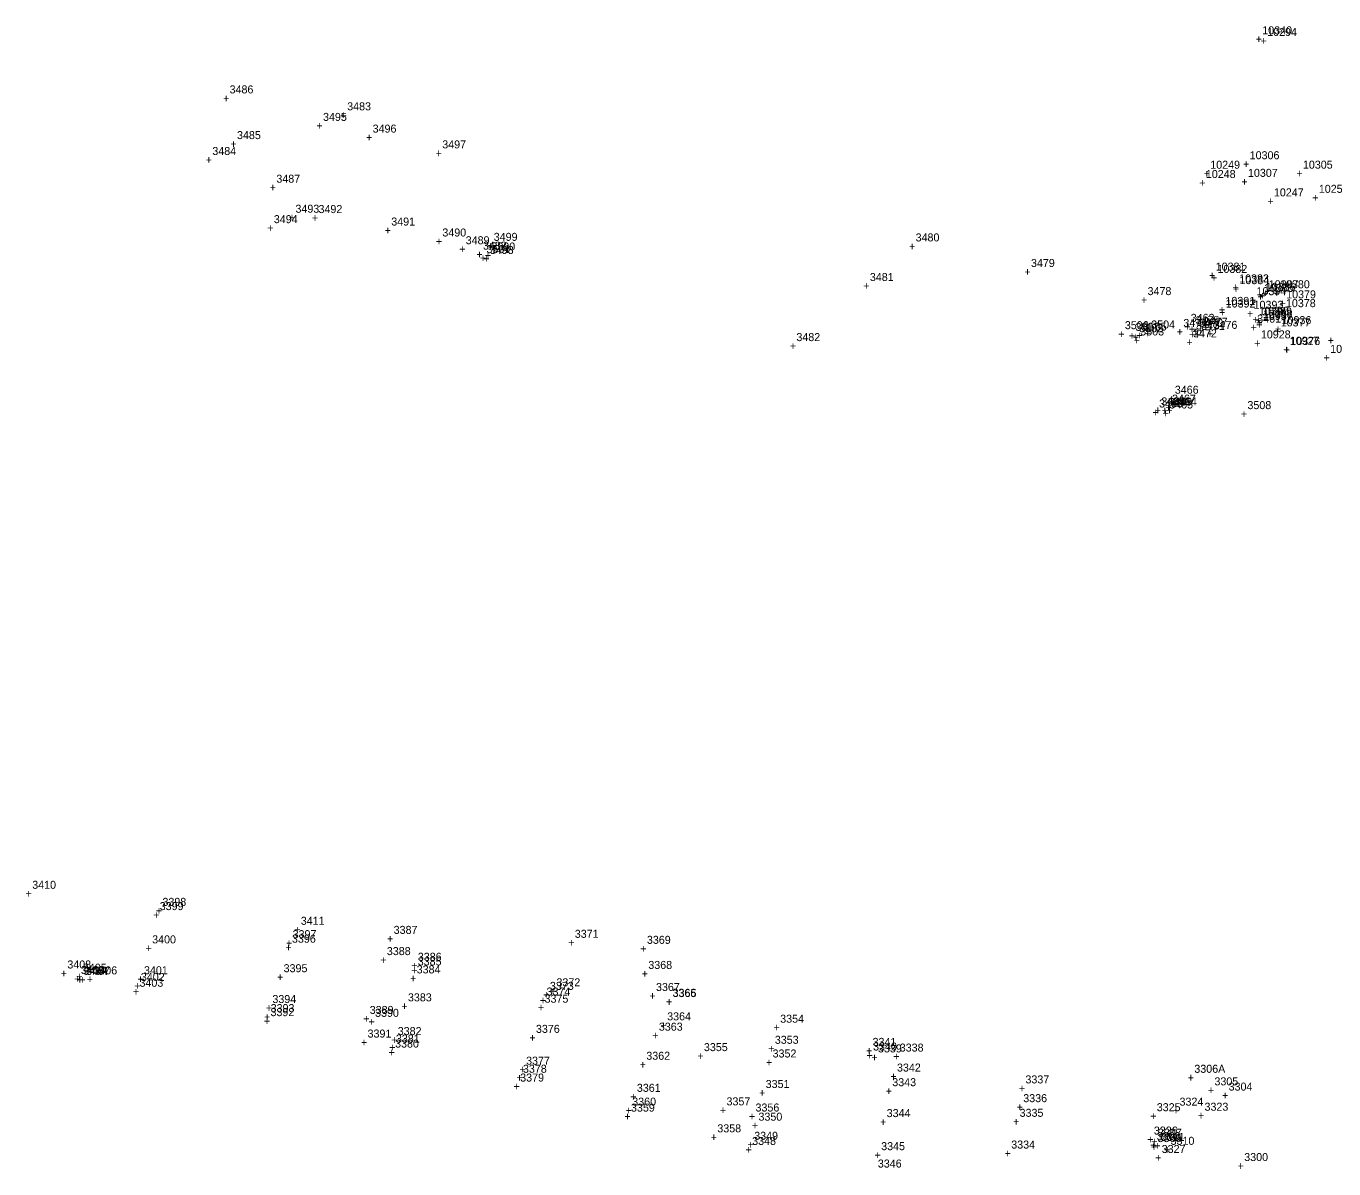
# Model space of a CAD drawing. Extents: x 1136220 to 1137808, y 528804 to 531215.
# Drawn here: x 1136511.5 to 1136920.1, y 529888.9 to 530245.8 of the extents above; entities that cross this region are included whole.
import ezdxf

# ---------------------------------------------------------------- set-up
doc = ezdxf.new("R2010")
doc.units = 0
for name, color, linetype in [('S_Drainage_CB', 7, 'Continuous'), ('S_Drainage_Culvert_Top', 7, 'Continuous'), ('S_Drainage_Invert', 7, 'Continuous'), ('S_Drainage_MH', 7, 'Continuous'), ('S_Drainage_Sump', 7, 'Continuous'), ('S_Fencing_Page', 7, 'Continuous'), ('S_Ground_Elevation', 7, 'Continuous'), ('S_Property_Garden', 7, 'Continuous'), ('S_Railroad_Signal', 7, 'Continuous'), ('S_Railroad_Tracks', 7, 'Continuous'), ('S_RetWall_Top', 7, 'Continuous'), ('S_Roadway_Centerline', 7, 'Continuous'), ('S_Roadway_Drive_Paved', 7, 'Continuous'), ('S_Roadway_Edge_Pavement', 7, 'Continuous'), ('S_Roadway_Sidewalks', 7, 'Continuous'), ('S_Traffic_Sign_DoublePost', 7, 'Continuous'), ('S_Utilities_Gas_Gate', 7, 'Continuous'), ('S_Utilities_UG_Gas_Line', 7, 'Continuous'), ('S_Utilities_UG_Sanitary_MH', 7, 'Continuous'), ('S_Utilities_UG_Water_Gate', 7, 'Continuous'), ('S_Utilities_UG_Water_Line', 7, 'Continuous'), ('S_Utilities_UG_Water_Shutoff', 7, 'Continuous')]:
    doc.layers.add(name, color=color, linetype=linetype)

msp = doc.modelspace()

# ---------------------------------------------------------------- texts
at = {"layer": 'S_Drainage_CB'}
for s, p in [('+', (1136654.33, 530171.88)), ('3498', (1136656.39, 530174.63)), ('3470', (1136878.04, 530151.91)), ('+', (1136875.97, 530149.16)), ('3464', (1136869.84, 530127.3)), ('+', (1136867.77, 530124.55)), ('3404', (1136529.39, 529949.46)), ('+', (1136527.33, 529946.71)), ('3308', (1136864.74, 529897.79)), ('+', (1136862.68, 529895.04))]:
    msp.add_text(s, height=2.5, dxfattribs=at).set_placement(p)
at = {"layer": 'S_Drainage_Culvert_Top'}
for s, p in [('+', (1136655.55, 530175.97)), ('3499', (1136657.61, 530178.72)), ('3506', (1136854.79, 530151.13)), ('3504', (1136863.03, 530151.35)), ('3474', (1136873.06, 530151.83)), ('3476', (1136882.51, 530151.23)), ('+', (1136852.73, 530148.38)), ('+', (1136860.97, 530148.6)), ('+', (1136871, 530149.08)), ('3472', (1136876.09, 530148.57)), ('+', (1136880.45, 530148.48)), ('+', (1136874.03, 530145.82)), ('3466', (1136870.4, 530130.96)), ('3468', (1136865.48, 530126.67)), ('+', (1136868.34, 530128.21)), ('+', (1136863.42, 530123.92)), ('3408', (1136524.4, 529951.44)), ('+', (1136522.33, 529948.69)), ('3406', (1136532.53, 529949.6)), ('+', (1136530.47, 529946.85)), ('3306A', (1136876.5, 529918.85)), ('+', (1136874.44, 529916.1)), ('3310', (1136869.08, 529896.36)), ('+', (1136867.02, 529893.61))]:
    msp.add_text(s, height=2.5, dxfattribs=at).set_placement(p)
at = {"layer": 'S_Drainage_Invert'}
for s, p in [('3500', (1136656.88, 530175.71)), ('+', (1136654.82, 530172.96)), ('3475', (1136876.88, 530152.67)), ('3473', (1136876.95, 530151.04)), ('3477', (1136879.48, 530152.22)), ('+', (1136856.04, 530147.86)), ('3507', (1136858.1, 530150.61)), ('+', (1136858.33, 530147.95)), ('3505', (1136860.4, 530150.7)), ('+', (1136874.82, 530149.92)), ('+', (1136874.89, 530148.29)), ('+', (1136877.42, 530149.47)), ('3469', (1136868.37, 530127.23)), ('3467', (1136869.53, 530128.18)), ('+', (1136866.31, 530124.48)), ('+', (1136867.46, 530125.43)), ('+', (1136526.57, 529946.96)), ('3409', (1136528.63, 529949.71)), ('3407', (1136530.25, 529949.43)), ('+', (1136528.18, 529946.68)), ('3306', (1136876.5, 529918.88)), ('+', (1136874.44, 529916.13)), ('3307', (1136865.12, 529898.89)), ('3311', (1136866.01, 529897.6)), ('+', (1136863.05, 529896.14)), ('+', (1136863.94, 529894.85))]:
    msp.add_text(s, height=2.5, dxfattribs=at).set_placement(p)
at = {"layer": 'S_Drainage_MH'}
for s, p in [('+', (1136857.23, 530147.41)), ('3502', (1136859.29, 530150.16))]:
    msp.add_text(s, height=2.5, dxfattribs=at).set_placement(p)
at = {"layer": 'S_Drainage_Sump'}
for s, p in [('+', (1136653.27, 530172.13)), ('3501', (1136655.33, 530174.88)), ('3471', (1136878.62, 530150.9)), ('3503', (1136859.6, 530149.17)), ('+', (1136876.56, 530148.15)), ('+', (1136857.54, 530146.42)), ('3465', (1136868.65, 530126.36)), ('+', (1136866.59, 530123.61)), ('+', (1136527.2, 529947.7)), ('3405', (1136529.26, 529950.44)), ('+', (1136862.95, 529894.47)), ('3309', (1136865.01, 529897.22))]:
    msp.add_text(s, height=2.5, dxfattribs=at).set_placement(p)
at = {"layer": 'S_Fencing_Page'}
for s, p in [('10294', (1136899.26, 530242.7)), ('+', (1136897.2, 530239.95)), ('10249', (1136881.48, 530201.24)), ('+', (1136879.42, 530198.49)), ('10250', (1136915.39, 530193.72)), ('+', (1136913.33, 530190.97))]:
    msp.add_text(s, height=2.5, dxfattribs=at).set_placement(p)
at = {"layer": 'S_Ground_Elevation'}
for s, p in [('10382', (1136883.73, 530168.7)), ('+', (1136881.66, 530165.95)), ('10387', (1136899.74, 530163.9)), ('+', (1136897.68, 530161.15)), ('+', (1136895.86, 530151.9)), ('10388', (1136897.92, 530154.65)), ('3399', (1136553.26, 529969.67)), ('+', (1136551.2, 529966.92)), ('3396', (1136594.58, 529959.49)), ('+', (1136592.52, 529956.74)), ('3385', (1136633.87, 529952.39)), ('3402', (1136547.36, 529947.53)), ('3401', (1136548.34, 529949.64)), ('+', (1136631.47, 529947.15)), ('+', (1136631.81, 529949.64)), ('3384', (1136633.54, 529949.9)), ('+', (1136545.3, 529944.78)), ('+', (1136546.28, 529946.89)), ('3374', (1136674.11, 529942.99)), ('3394', (1136588.46, 529940.64)), ('+', (1136672.05, 529940.24)), ('3375', (1136673.49, 529940.75)), ('+', (1136585.86, 529935.07)), ('+', (1136586.4, 529937.89)), ('3393', (1136587.92, 529937.82)), ('+', (1136671.42, 529938)), ('3364', (1136711.8, 529935.24)), ('3382', (1136627.62, 529930.64)), ('3363', (1136709.2, 529932.01)), ('+', (1136709.74, 529932.49)), ('+', (1136625.56, 529927.89)), ('3381', (1136627.05, 529928.3)), ('+', (1136707.14, 529929.26)), ('3353', (1136745.43, 529927.92)), ('+', (1136624.98, 529925.55)), ('+', (1136743.37, 529925.17)), ('3352', (1136744.74, 529923.64)), ('+', (1136665.66, 529918.64)), ('3378', (1136666.74, 529918.87)), ('3377', (1136667.72, 529921.39)), ('+', (1136742.67, 529920.89)), ('3342', (1136783.6, 529919.24)), ('+', (1136664.68, 529916.12)), ('+', (1136781.53, 529916.49)), ('3343', (1136782.13, 529914.67)), ('+', (1136700.26, 529910.16)), ('3361', (1136702.33, 529912.91)), ('+', (1136780.07, 529911.92)), ('3360', (1136700.89, 529908.6)), ('+', (1136820.99, 529906.93)), ('3336', (1136823.05, 529909.68)), ('+', (1136698.83, 529905.85)), ('3350', (1136740.33, 529903.9)), ('+', (1136819.85, 529902.36)), ('3335', (1136821.91, 529905.11)), ('+', (1136738.27, 529901.15)), ('3349', (1136739, 529897.93)), ('3326', (1136863.86, 529899.56)), ('+', (1136736.94, 529895.18)), ('3345', (1136778.66, 529894.69)), ('+', (1136861.8, 529896.81)), ('3327', (1136866.3, 529893.82)), ('+', (1136776.6, 529891.94)), ('+', (1136864.24, 529891.07)), ('3346', (1136777.62, 529889.26))]:
    msp.add_text(s, height=2.5, dxfattribs=at).set_placement(p)
at = {"layer": 'S_Property_Garden'}
for s, p in [('10306', (1136893.79, 530204.21)), ('+', (1136891.73, 530201.46)), ('10305', (1136910.42, 530201.27)), ('10307', (1136893.25, 530198.71)), ('+', (1136908.36, 530198.52)), ('+', (1136891.19, 530195.96)), ('10384', (1136890.6, 530165.2)), ('+', (1136888.53, 530162.45)), ('+', (1136896.21, 530160.03)), ('10385', (1136898.27, 530162.78)), ('+', (1136884.15, 530155.96)), ('10391', (1136886.21, 530158.71)), ('10390', (1136896.72, 530155.63)), ('+', (1136894.66, 530152.88))]:
    msp.add_text(s, height=2.5, dxfattribs=at).set_placement(p)
at = {"layer": 'S_Railroad_Signal'}
for s, p in [('3300', (1136892.09, 529891.29)), ('+', (1136890.03, 529888.54))]:
    msp.add_text(s, height=2.5, dxfattribs=at).set_placement(p)
at = {"layer": 'S_Railroad_Tracks'}
for s, p in [('3305', (1136882.78, 529914.93)), ('+', (1136880.72, 529912.18)), ('+', (1136885.15, 529910.55)), ('3304', (1136887.21, 529913.3))]:
    msp.add_text(s, height=2.5, dxfattribs=at).set_placement(p)
at = {"layer": 'S_RetWall_Top'}
for s, p in [('10383', (1136890.5, 530165.74)), ('10386', (1136898.81, 530163.1)), ('+', (1136888.44, 530162.99)), ('+', (1136896.75, 530160.35)), ('10392', (1136886.3, 530157.89)), ('10389', (1136897.69, 530155.42)), ('+', (1136884.24, 530155.14)), ('+', (1136895.63, 530152.67))]:
    msp.add_text(s, height=2.5, dxfattribs=at).set_placement(p)
at = {"layer": 'S_Roadway_Centerline'}
for s, p in [('3400', (1136550.9, 529959.28)), ('+', (1136548.84, 529956.53)), ('+', (1136589.91, 529947.52)), ('3395', (1136591.97, 529950.27)), ('3383', (1136630.81, 529941.17)), ('+', (1136628.75, 529938.42)), ('3376', (1136670.8, 529931.33)), ('+', (1136668.74, 529928.58)), ('3362', (1136705.28, 529922.93)), ('+', (1136703.22, 529920.18)), ('3351', (1136742.57, 529914.11)), ('+', (1136740.51, 529911.36)), ('+', (1136778.31, 529902.27)), ('3344', (1136780.38, 529905.02)), ('3334', (1136819.3, 529895.19)), ('+', (1136817.24, 529892.44))]:
    msp.add_text(s, height=2.5, dxfattribs=at).set_placement(p)
at = {"layer": 'S_Roadway_Drive_Paved'}
for s, p in [('10340', (1136897.73, 530243.24)), ('+', (1136895.67, 530240.49)), ('10248', (1136880.1, 530198.34)), ('+', (1136878.04, 530195.59)), ('10247', (1136901.36, 530192.61)), ('+', (1136899.3, 530189.86)), ('10381', (1136883.17, 530169.42)), ('+', (1136881.11, 530166.67)), ('10380', (1136903.27, 530163.91)), ('+', (1136901.21, 530161.16)), ('10379', (1136905.19, 530160.75)), ('+', (1136903.06, 530155.26)), ('+', (1136903.13, 530158)), ('10378', (1136905.12, 530158.01)), ('10377', (1136903.5, 530151.99)), ('10936', (1136903.76, 530152.71)), ('+', (1136901.44, 530149.24)), ('+', (1136901.69, 530149.96)), ('+', (1136904.45, 530143.42)), ('10376', (1136906.51, 530146.17)), ('+', (1136918.18, 530146.4))]:
    msp.add_text(s, height=2.5, dxfattribs=at).set_placement(p)
at = {"layer": 'S_Roadway_Edge_Pavement'}
for s, p in [('3495', (1136604.28, 530216.18)), ('+', (1136602.22, 530213.43)), ('3496', (1136619.78, 530212.53)), ('+', (1136617.72, 530209.78)), ('+', (1136639.47, 530204.85)), ('3497', (1136641.53, 530207.6)), ('3494', (1136588.91, 530184.25)), ('+', (1136593.61, 530184.75)), ('3493', (1136595.67, 530187.5)), ('+', (1136600.81, 530184.65)), ('3492', (1136602.87, 530187.4)), ('3491', (1136625.6, 530183.5)), ('+', (1136586.85, 530181.5)), ('+', (1136623.54, 530180.75)), ('3490', (1136641.57, 530180.08)), ('+', (1136639.51, 530177.33)), ('3489', (1136648.86, 530177.66)), ('3488', (1136654.24, 530175.98)), ('+', (1136646.8, 530174.91)), ('+', (1136652.18, 530173.23)), ('3462', (1136875.37, 530153.42)), ('+', (1136873.31, 530150.67)), ('10928', (1136897.29, 530148.25)), ('+', (1136895.23, 530145.5)), ('+', (1136904.25, 530143.53)), ('10927', (1136906.31, 530146.28)), ('10926', (1136918.94, 530143.72)), ('+', (1136916.88, 530140.97)), ('3463', (1136866.19, 530127.32)), ('+', (1136864.13, 530124.57)), ('3398', (1136554.11, 529971)), ('+', (1136552.05, 529968.25)), ('3397', (1136594.78, 529960.91)), ('3371', (1136682.93, 529961.02)), ('3369', (1136705.47, 529959.14)), ('+', (1136592.71, 529958.16)), ('+', (1136680.86, 529958.27)), ('+', (1136703.4, 529956.39)), ('+', (1136631.84, 529951.1)), ('3386', (1136633.9, 529953.85)), ('3368', (1136705.91, 529951.3)), ('+', (1136703.85, 529948.55)), ('+', (1136544.88, 529942.98)), ('3403', (1136546.94, 529945.73)), ('3373', (1136675.17, 529944.76)), ('+', (1136675.15, 529943.13)), ('3372', (1136677.21, 529945.88)), ('3367', (1136708.31, 529944.41)), ('3366', (1136713.45, 529942.6)), ('3365', (1136713.52, 529942.51)), ('+', (1136673.1, 529942.01)), ('+', (1136706.25, 529941.66)), ('+', (1136711.39, 529939.85)), ('+', (1136711.46, 529939.76)), ('3392', (1136587.86, 529936.55)), ('3354', (1136747.11, 529934.5)), ('+', (1136585.8, 529933.8)), ('+', (1136745.05, 529931.75)), ('3380', (1136626.8, 529926.73)), ('+', (1136624.74, 529923.98)), ('+', (1136782.4, 529922.73)), ('3338', (1136784.46, 529925.48)), ('3379', (1136665.88, 529916.12)), ('3337', (1136823.73, 529915.54)), ('+', (1136663.82, 529913.37)), ('+', (1136821.67, 529912.79)), ('3359', (1136700.49, 529906.73)), ('3325', (1136864.76, 529906.86)), ('3324', (1136871.88, 529908.59)), ('3323', (1136879.68, 529907.01)), ('+', (1136698.43, 529903.98)), ('+', (1136862.7, 529904.11)), ('+', (1136869.82, 529905.84)), ('+', (1136877.62, 529904.26)), ('3348', (1136738.36, 529896.32)), ('+', (1136736.3, 529893.57))]:
    msp.add_text(s, height=2.5, dxfattribs=at).set_placement(p)
at = {"layer": 'S_Roadway_Sidewalks'}
for s, p in [('+', (1136895.86, 530151.28)), ('10937', (1136897.92, 530154.03))]:
    msp.add_text(s, height=2.5, dxfattribs=at).set_placement(p)
at = {"layer": 'S_Traffic_Sign_DoublePost'}
for s, p in [('10394', (1136895.92, 530161.75)), ('+', (1136893.86, 530159)), ('10393', (1136895.01, 530157.5)), ('+', (1136892.95, 530154.75))]:
    msp.add_text(s, height=2.5, dxfattribs=at).set_placement(p)
at = {"layer": 'S_Utilities_Gas_Gate'}
for s, p in [('3461', (1136896.15, 530153.17)), ('+', (1136894.09, 530150.42))]:
    msp.add_text(s, height=2.5, dxfattribs=at).set_placement(p)
at = {"layer": 'S_Utilities_UG_Gas_Line'}
for s, p in [('+', (1136609.77, 530216.74)), ('3483', (1136611.83, 530219.49)), ('+', (1136787.36, 530175.79)), ('3480', (1136789.42, 530178.54)), ('+', (1136823.4, 530167.8)), ('3479', (1136825.46, 530170.55)), ('3478', (1136861.89, 530161.77)), ('+', (1136859.83, 530159.02)), ('3411', (1136597.33, 529965.09)), ('+', (1136595.27, 529962.34)), ('3341', (1136775.98, 529927.26)), ('+', (1136773.92, 529924.51)), ('+', (1136774.07, 529923.07)), ('+', (1136775.6, 529922.47)), ('3340', (1136776.13, 529925.82)), ('3339', (1136777.66, 529925.22))]:
    msp.add_text(s, height=2.5, dxfattribs=at).set_placement(p)
at = {"layer": 'S_Utilities_UG_Sanitary_MH'}
for s, p in [('3487', (1136589.7, 530196.88)), ('+', (1136587.63, 530194.13)), ('+', (1136891.03, 530123.41)), ('3508', (1136893.09, 530126.16)), ('3410', (1136513.43, 529976.33)), ('+', (1136511.37, 529973.58)), ('+', (1136721.22, 529922.88)), ('3355', (1136723.28, 529925.63))]:
    msp.add_text(s, height=2.5, dxfattribs=at).set_placement(p)
at = {"layer": 'S_Utilities_UG_Water_Gate'}
for s, p in [('3486', (1136575.09, 530224.77)), ('+', (1136573.03, 530222.02)), ('3485', (1136577.41, 530210.5)), ('3484', (1136569.7, 530205.53)), ('+', (1136575.35, 530207.75)), ('+', (1136567.63, 530202.78)), ('3481', (1136775.13, 530166.17)), ('+', (1136773.06, 530163.42)), ('3482', (1136752.17, 530147.41)), ('+', (1136750.11, 530144.66))]:
    msp.add_text(s, height=2.5, dxfattribs=at).set_placement(p)
at = {"layer": 'S_Utilities_UG_Water_Line'}
for s, p in [('+', (1136624.29, 529959.5)), ('3387', (1136626.35, 529962.25)), ('3389', (1136618.87, 529937.24)), ('3390', (1136620.54, 529936.34)), ('+', (1136616.81, 529934.49)), ('+', (1136618.48, 529933.59)), ('+', (1136616.14, 529927.11)), ('3391', (1136618.2, 529929.86)), ('3357', (1136730.34, 529908.68)), ('3356', (1136739.4, 529906.76)), ('+', (1136728.27, 529905.93)), ('+', (1136737.34, 529904.01)), ('3358', (1136727.47, 529900.26)), ('+', (1136725.41, 529897.51))]:
    msp.add_text(s, height=2.5, dxfattribs=at).set_placement(p)
at = {"layer": 'S_Utilities_UG_Water_Shutoff'}
for s, p in [('3388', (1136624.22, 529955.62)), ('+', (1136622.16, 529952.87))]:
    msp.add_text(s, height=2.5, dxfattribs=at).set_placement(p)

doc.saveas('drawing.dxf')
